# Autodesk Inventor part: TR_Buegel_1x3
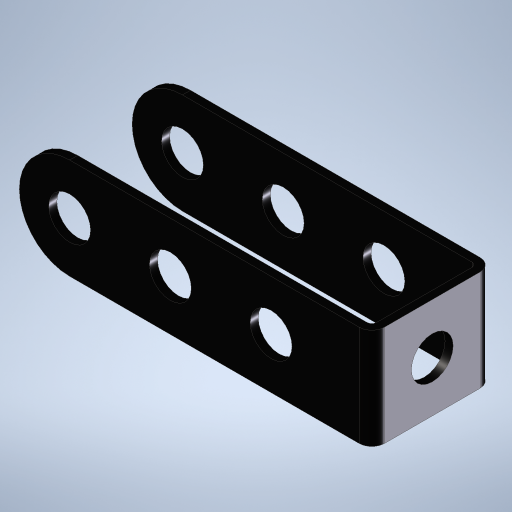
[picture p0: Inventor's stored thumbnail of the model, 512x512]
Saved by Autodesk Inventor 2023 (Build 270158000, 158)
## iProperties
Created: 2023-11
Part Number: TR_Buegel_1x3
Material: Edelstahl
Document SubType Name: Modeling
Designer: Admin
Density: 8 g/cm^3
Appearance: Halbpoliert
Author: Admin
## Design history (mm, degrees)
sketch "Skizze1"
  geometry: L1 (35, 6)-(1.25, 6); L2 (0, 4.75)-(0, -4.75); L3 (1.25, -6)-(35, -6); L4 (35, -6)-(35, -5.2); L5 (35, -5.2)-(1.25, -5.2); L6 (0.8, -4.75)-(0.8, 4.75); L7 (1.25, 5.2)-(35, 5.2); L8 (35, 5.2)-(35, 6); A1 r 1.25 centre (1.25, 4.75) between (1.25, 6) and (0, 4.75); A2 r 1.25 centre (1.25, -4.75) between (0, -4.75) and (1.25, -6); A3 r 0.45 centre (1.25, 4.75) between (1.25, 5.2) and (0.8, 4.75); A4 r 0.45 centre (1.25, -4.75) between (0.8, -4.75) and (1.25, -5.2); 5 further points
  constraints: 16 end point, 8 point on circle, 8 tangent, 4 centre point, 4 point on line, 3 horizontal, 3 perpendicular, 2 equal radius, 2 midpoint, 2 vertical alignment, 1 coincident, 1 collinear, 1 horizontal alignment, 1 parallel, 1 vertical
  dimensions: "d0" = 0.8 distance of L7.end L1.start (= Dicke); "d1" = 35 horizontal distance of point (0, 0) L1.start (computed from Einheitsmaß, HochLoch); "d2" = 0.8 horizontal distance of point (0, 0) point (0.8, 5.2) (= Dicke); "d6" = 1.25 radius of A1; "d7" = 12 distance of L3.end L1.start
extrude "Extrusion1" new body sketch "Skizze1" stored distance "d8" = 10 (= Einheitsmaß); taper "d9" = 0 deg
fillet "Rundung1" dims "d10" = 5 (= 0.5 x Einheitsmaß)
sketch "Skizze2"
  geometry: C1 r 2.075 at (-30, 0); A1 r 5 centre (-30, 0) between (-30, 5) and (-30, -5) reference; 1 further point
  constraints: 1 centre point, 1 coincident
  dimensions: "d11" = 4.15 diameter of C1 (= 2 x Radius)
extrude "Extrusion2" cut sketch "Skizze2" extent not by distance; stored distance "d12" = 0; taper "d13" = 0 deg
pattern_linear "Rechteckige Anordnung1" dims "d19" = 10 (= Einheitsmaß)
sketch "Skizze3"
  geometry: C1 r 2.075 at (0, 0); 1 further point
  constraints: 1 centre point, 1 coincident
  dimensions: "d14" = 4.15 diameter of C1 (= 2 x Radius)
extrude "Extrusion3" cut sketch "Skizze3" extent not by distance; stored distance "d15" = 0; taper "d16" = 0 deg
node "Volumenkörper1"
other parameters: "Einheitsmaß" = 10 [user parameter; used in 4 equation terms], "Radius" = 2.075 [user parameter; used in 2 equation terms], "Fasen" = 0.5 [user parameter], "Dicke" = 0.8 [user parameter; used in 2 equation terms]
